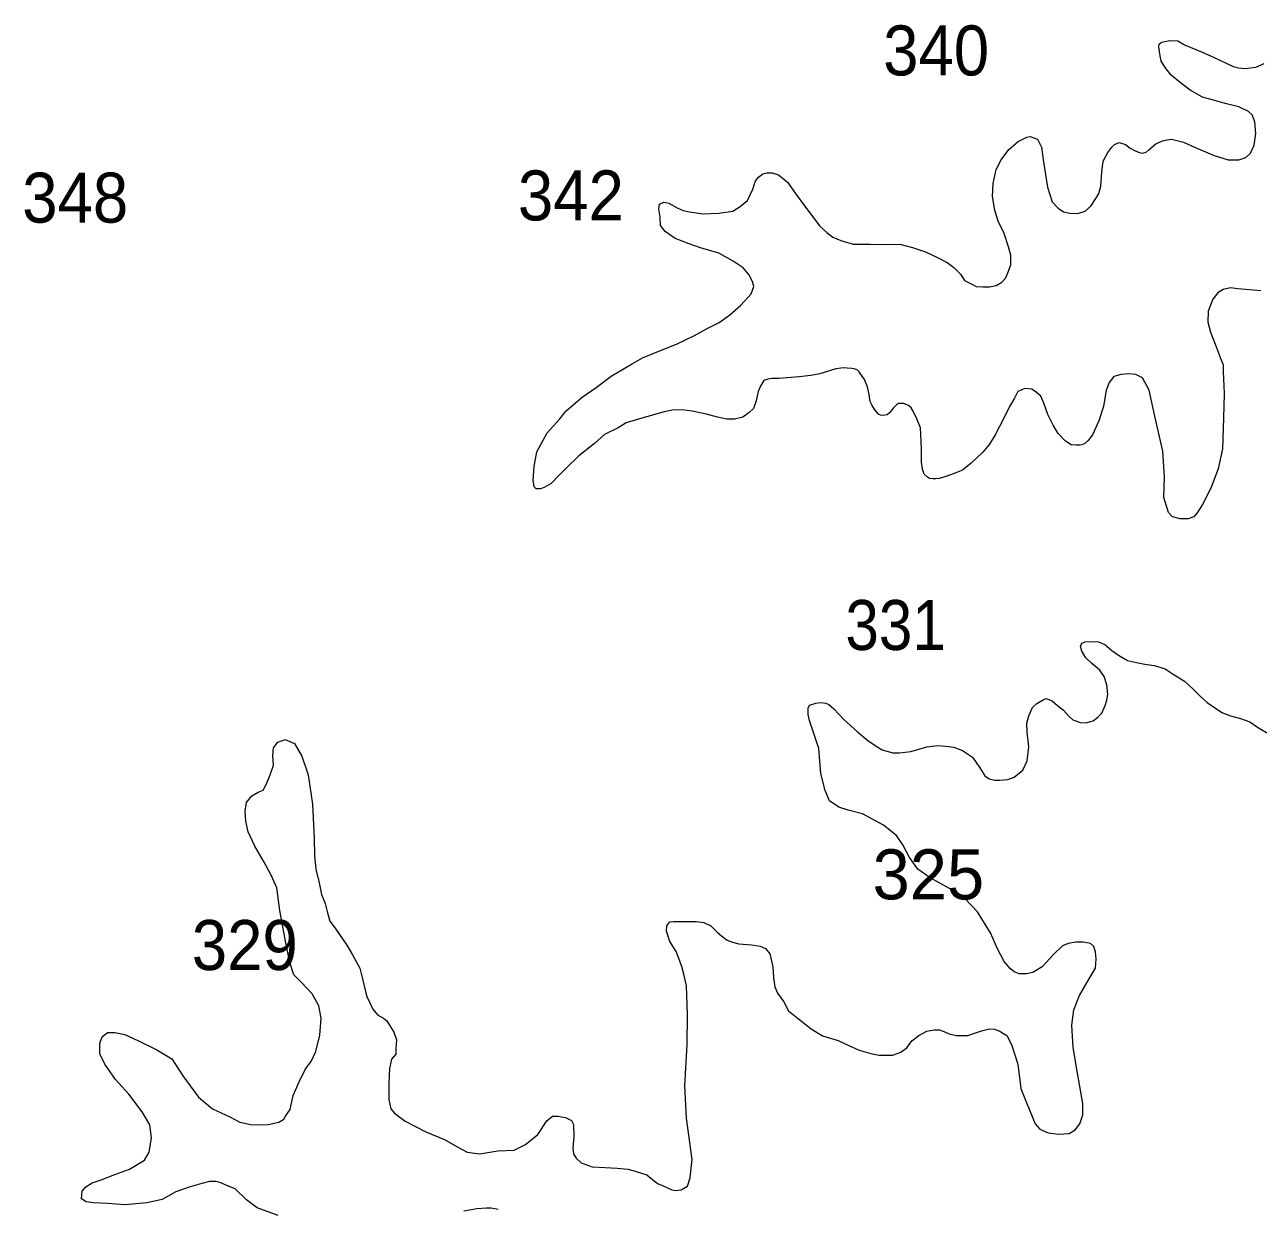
# Model space of a CAD drawing. Extents: x 445.4 to 500, y 8728.7 to 8784.
# Drawn here: x 464.834 to 468.782, y 8737.917 to 8741.707 of the extents above; entities that cross this region are included whole.
import ezdxf

# ---------------------------------------------------------------- set-up
doc = ezdxf.new("R2010")
doc.units = 0
doc.header["$LTSCALE"] = 0.064
doc.layers.add('2', color=7, linetype='Continuous', lineweight=13)
doc.layers.add('21', color=7, linetype='Continuous')

msp = doc.modelspace()

# ---------------------------------------------------------------- linework, layer by layer
at = {"layer": '2'}
for points in [[(468.4106, 8741.2963), (468.4239, 8741.2992), (468.4327, 8741.3081), (468.4547, 8741.3257), (468.4753, 8741.3359), (468.49, 8741.3389), (468.5048, 8741.3403), (468.543, 8741.3315), (468.5783, 8741.3154), (468.6415, 8741.289), (468.6864, 8741.2742), (468.7202, 8741.2742), (468.7423, 8741.2816), (468.757, 8741.2963), (468.7688, 8741.3212), (468.7746, 8741.3594), (468.7717, 8741.3961), (468.7629, 8741.4181), (468.7511, 8741.4298), (468.7202, 8741.4445), (468.6805, 8741.4533), (468.6349, 8741.4665), (468.604, 8741.4753), (468.5643, 8741.4974), (468.532, 8741.5223), (468.5038, 8741.5452), (468.4876, 8741.5658), (468.4714, 8741.5907), (468.467, 8741.6142), (468.4641, 8741.6362), (468.4656, 8741.645), (468.4729, 8741.6509), (468.4994, 8741.6568), (468.5244, 8741.6553), (468.5464, 8741.6421), (468.6009, 8741.6201), (468.6406, 8741.6025), (468.6773, 8741.5849), (468.7023, 8741.5731), (468.7185, 8741.5687), (468.7406, 8741.5672), (468.7744, 8741.5716), (468.8009, 8741.5834)], [(467.0162, 8740.7334), (467.0574, 8740.754), (467.0912, 8740.7789), (467.1265, 8740.8097), (467.1589, 8740.8464), (467.168, 8740.8693), (467.1636, 8740.8854), (467.1518, 8740.9074), (467.1342, 8740.9294), (467.1018, 8740.95), (467.0563, 8740.9764), (466.9974, 8740.9926), (466.9607, 8741.0058), (466.9165, 8741.0234), (466.8842, 8741.0454), (466.8695, 8741.0645), (466.8678, 8741.0918), (466.8634, 8741.1182), (466.8663, 8741.1329), (466.8796, 8741.1387), (466.8957, 8741.1358), (466.9222, 8741.1211), (466.9413, 8741.1123), (466.9619, 8741.1079), (467.0046, 8741.1021), (467.056, 8741.1035), (467.1002, 8741.1109), (467.1237, 8741.1255), (467.1472, 8741.1446), (467.1649, 8741.1813), (467.1737, 8741.2077), (467.1825, 8741.2195), (467.1972, 8741.2298), (467.209, 8741.2327), (467.2266, 8741.2327), (467.2472, 8741.2268), (467.2752, 8741.2033), (467.3031, 8741.1637), (467.3296, 8741.127), (467.3796, 8741.0624), (467.4016, 8741.0419), (467.4208, 8741.0272), (467.4458, 8741.0169), (467.4863, 8741.0047), (467.5393, 8741.0047), (467.5893, 8741.0033), (467.6349, 8741.0047), (467.676, 8740.9945), (467.7172, 8740.9798), (467.7555, 8740.9622), (467.7863, 8740.946), (467.8084, 8740.9299), (467.829, 8740.9093), (467.8422, 8740.8888), (467.8672, 8740.8756), (467.879, 8740.8697), (467.901, 8740.8682), (467.9216, 8740.8682), (467.9437, 8740.8726), (467.9613, 8740.8829), (467.9746, 8740.8976), (467.9834, 8740.9181), (467.9908, 8740.9387), (467.9908, 8740.9695), (467.9834, 8740.9959), (467.9687, 8741.0385), (467.9496, 8741.0781), (467.9393, 8741.1134), (467.9319, 8741.1574), (467.9334, 8741.1985), (467.9437, 8741.244), (467.9591, 8741.2743), (467.9841, 8741.3081), (468.0135, 8741.333), (468.0415, 8741.3477), (468.0518, 8741.3492), (468.0753, 8741.3403), (468.0886, 8741.3154), (468.0944, 8741.2684), (468.1077, 8741.1877), (468.1224, 8741.1407), (468.1415, 8741.1202), (468.1591, 8741.1084), (468.1797, 8741.104), (468.2047, 8741.1026), (468.2283, 8741.1099), (468.2459, 8741.126), (468.265, 8741.1539), (468.2724, 8741.1671), (468.2783, 8741.1906), (468.2812, 8741.2347), (468.2856, 8741.2699), (468.3003, 8741.2978), (468.3136, 8741.3154), (468.3224, 8741.3242), (468.3371, 8741.3301), (468.3577, 8741.3242), (468.3724, 8741.3125), (468.3886, 8741.3036), (468.4018, 8741.2978), (468.4106, 8741.2963)], [(468.7901, 8740.8559), (468.7171, 8740.8614), (468.6934, 8740.865), (468.6696, 8740.8596), (468.6532, 8740.8486), (468.6368, 8740.8286), (468.6222, 8740.7903), (468.6204, 8740.7557), (468.6295, 8740.7229), (468.6459, 8740.6792), (468.6623, 8740.6373), (468.6696, 8740.6191), (468.6696, 8740.5972), (468.6732, 8740.5271), (468.6714, 8740.4487), (468.6678, 8740.3503), (468.6534, 8740.2861), (468.6305, 8740.2237), (468.6034, 8740.1718), (468.5867, 8740.1447), (468.5763, 8740.1323), (468.5576, 8740.126), (468.5326, 8740.126), (468.5076, 8740.1323), (468.4951, 8740.1468), (468.4805, 8740.1946), (468.4826, 8740.2591), (468.4763, 8740.3423), (468.4513, 8740.4545), (468.4326, 8740.5377), (468.4117, 8740.5772), (468.3909, 8740.5876), (468.3659, 8740.5897), (468.343, 8740.5876), (468.3201, 8740.5814), (468.3055, 8740.5627), (468.2951, 8740.5377), (468.2867, 8740.4857), (468.2722, 8740.44), (468.2521, 8740.3947), (468.2381, 8740.3771), (468.2269, 8740.3668), (468.2176, 8740.3631), (468.2111, 8740.3613), (468.1999, 8740.3613), (468.1831, 8740.3631), (468.1654, 8740.3743), (468.1421, 8740.3994), (468.1254, 8740.4254), (468.1086, 8740.4598), (468.0955, 8740.4961), (468.0862, 8740.5184), (468.0723, 8740.5305), (468.0573, 8740.5408), (468.035, 8740.5426), (468.0257, 8740.5389)], [(468.0257, 8740.5389), (468.0126, 8740.5333), (468.0024, 8740.5119), (467.9856, 8740.4859), (467.9679, 8740.4478), (467.9399, 8740.3947), (467.9222, 8740.365), (467.9008, 8740.3389), (467.8635, 8740.3045), (467.836, 8740.2818), (467.809, 8740.2707), (467.7791, 8740.2605), (467.7605, 8740.2549), (467.7503, 8740.2539), (467.7409, 8740.2539), (467.7298, 8740.2549), (467.7232, 8740.2595), (467.713, 8740.2688), (467.7074, 8740.2846), (467.7046, 8740.307), (467.7046, 8740.3488), (467.7027, 8740.3962), (467.7009, 8740.4176), (467.6897, 8740.4455), (467.6776, 8740.4703), (467.6711, 8740.4815), (467.6627, 8740.4889), (467.6552, 8740.4917), (467.6468, 8740.4945), (467.6375, 8740.4954), (467.631, 8740.4945), (467.6245, 8740.4908), (467.6133, 8740.4796), (467.603, 8740.4666), (467.5946, 8740.4592), (467.5872, 8740.4573), (467.5807, 8740.4564), (467.5732, 8740.4573), (467.5667, 8740.461), (467.5546, 8740.475), (467.5462, 8740.4889), (467.5406, 8740.5019), (467.5369, 8740.5243), (467.5313, 8740.5484), (467.522, 8740.5717), (467.5052, 8740.5959), (467.4987, 8740.6024), (467.4921, 8740.6052), (467.4819, 8740.607), (467.4661, 8740.608), (467.4549, 8740.6089), (467.4308, 8740.6062), (467.3796, 8740.5904), (467.3498, 8740.5848), (467.3134, 8740.5802), (467.2474, 8740.5745), (467.2254, 8740.5745), (467.2122, 8740.573), (467.2004, 8740.5686), (467.1901, 8740.5524), (467.1813, 8740.5334), (467.1754, 8740.504), (467.1666, 8740.479), (467.1533, 8740.4658), (467.1327, 8740.4512), (467.1063, 8740.4453), (467.0813, 8740.4453), (467.0518, 8740.4512), (467.0166, 8740.4614), (466.971, 8740.4702), (466.9386, 8740.4746), (466.9063, 8740.4732), (466.8768, 8740.4673), (466.7915, 8740.4423), (466.7592, 8740.4335), (466.7342, 8740.4174), (466.6901, 8740.3954), (466.6577, 8740.3675), (466.6077, 8740.3279), (466.5673, 8740.2876), (466.5453, 8740.2656), (466.5188, 8740.2392), (466.4967, 8740.226), (466.485, 8740.2216), (466.4717, 8740.2216), (466.4644, 8740.2289), (466.4614, 8740.2495), (466.4644, 8740.2935), (466.4732, 8740.3405), (466.507, 8740.4007), (466.5467, 8740.4462), (466.5673, 8740.4711), (466.6188, 8740.5152), (466.6629, 8740.546), (466.7118, 8740.5822), (466.7765, 8740.6204), (466.8118, 8740.6409), (466.8692, 8740.6644), (466.9206, 8740.685), (466.978, 8740.7129), (467.0162, 8740.7334)], [(468.1892, 8739.4832), (468.2135, 8739.4747), (468.2305, 8739.4735), (468.2535, 8739.4795), (468.2693, 8739.4917), (468.2814, 8739.5038), (468.2923, 8739.5292), (468.2972, 8739.5461), (468.3008, 8739.5643), (468.2972, 8739.5946), (468.2887, 8739.6212), (468.2753, 8739.6418), (468.2499, 8739.6636), (468.2305, 8739.6818), (468.2174, 8739.703), (468.2137, 8739.7187), (468.2174, 8739.7284), (468.2283, 8739.732), (468.2489, 8739.7332), (468.2708, 8739.732), (468.2914, 8739.7236), (468.3132, 8739.7042), (468.3351, 8739.6897), (468.3642, 8739.6727), (468.3921, 8739.6666), (468.4188, 8739.6606), (468.4491, 8739.657), (468.4843, 8739.6461), (468.5097, 8739.6291), (468.5461, 8739.6061), (468.5728, 8739.5819), (468.5973, 8739.5573), (468.6191, 8739.5379), (468.6422, 8739.5222), (468.6652, 8739.5065), (468.6931, 8739.4956), (468.7259, 8739.4871), (468.755, 8739.4762), (468.7793, 8739.4592), (468.8195, 8739.4358)], [(467.9776, 8738.473), (467.9925, 8738.4446), (468.0131, 8738.3808), (468.0228, 8738.3038), (468.0421, 8738.2556), (468.0686, 8738.1906), (468.0831, 8738.1737), (468.1096, 8738.1617), (468.1434, 8738.1569), (468.1772, 8738.1593), (468.1965, 8738.1713), (468.211, 8738.1906), (468.2206, 8738.2195), (468.2206, 8738.2556), (468.2037, 8738.3519), (468.1901, 8738.4341), (468.1861, 8738.5056), (468.192, 8738.5552), (468.2099, 8738.6008), (468.2378, 8738.6485), (468.2617, 8738.6882), (468.2636, 8738.718), (468.2617, 8738.7398), (468.2557, 8738.7577), (468.2457, 8738.7676), (468.2219, 8738.7716), (468.198, 8738.7716), (468.1741, 8738.7676), (468.1562, 8738.7596), (468.1264, 8738.7319), (468.0906, 8738.6922), (468.0608, 8738.6743), (468.0409, 8738.6703), (468.017, 8738.6703), (468.0011, 8738.6763), (467.9892, 8738.6862), (467.9693, 8738.71), (467.9474, 8738.7497), (467.9255, 8738.8013), (467.8838, 8738.8688), (467.844, 8738.9105), (467.7938, 8738.9436), (467.7322, 8738.9773), (467.6924, 8739.0051), (467.6665, 8739.0428), (467.6447, 8739.0825), (467.6248, 8739.1123), (467.583, 8739.146), (467.5154, 8739.1818), (467.4697, 8739.1937), (467.4398, 8739.2036), (467.41, 8739.2234), (467.3961, 8739.2572), (467.3822, 8739.3108), (467.376, 8739.391), (467.3621, 8739.4327), (467.3461, 8739.4804), (467.3422, 8739.5002), (467.3422, 8739.5201), (467.3461, 8739.53), (467.366, 8739.536), (467.3819, 8739.5379), (467.3979, 8739.536), (467.4078, 8739.532), (467.4237, 8739.5181), (467.4555, 8739.4843), (467.4993, 8739.4446), (467.5331, 8739.4169), (467.5589, 8739.399), (467.5788, 8739.3871), (467.6126, 8739.3772), (467.6345, 8739.3772), (467.6703, 8739.3811), (467.722, 8739.397), (467.7558, 8739.401), (467.7817, 8739.399), (467.8075, 8739.395), (467.8354, 8739.3851), (467.8672, 8739.3633), (467.8911, 8739.3295), (467.907, 8739.3037), (467.9209, 8739.2938), (467.9388, 8739.2898), (467.9547, 8739.2898), (467.9806, 8739.2918), (468.0005, 8739.2997), (468.0283, 8739.3216), (468.0422, 8739.3513), (468.0482, 8739.397), (468.0424, 8739.4432), (468.0412, 8739.4723), (468.0485, 8739.4953), (468.0594, 8739.5219), (468.074, 8739.5352), (468.0934, 8739.5474), (468.1031, 8739.551), (468.1225, 8739.5437), (468.1395, 8739.5292), (468.1589, 8739.5134), (468.1747, 8739.4953), (468.1892, 8739.4832)], [(465.0998, 8737.9354), (465.0543, 8737.9373), (465.0315, 8737.941), (465.0163, 8737.9505), (465.0182, 8737.9751), (465.0296, 8737.9884), (465.0505, 8738.0017), (465.079, 8738.0111), (465.1226, 8738.0282), (465.17, 8738.0452), (465.2175, 8738.0736), (465.2327, 8738.1001), (465.2403, 8738.1456), (465.2346, 8738.1873), (465.2099, 8738.2289), (465.1681, 8738.2857), (465.1245, 8738.3324), (465.0904, 8738.3817), (465.0752, 8738.4139), (465.0752, 8738.448), (465.0828, 8738.4688), (465.0998, 8738.4821), (465.1226, 8738.4821), (465.1549, 8738.4764), (465.1985, 8738.4555), (465.2573, 8738.4271), (465.3048, 8738.3987), (465.3408, 8738.3438), (465.3902, 8738.2756), (465.4357, 8738.2378), (465.4907, 8738.2131), (465.523, 8738.1961), (465.5572, 8738.1885), (465.5837, 8738.1866), (465.6141, 8738.1885), (465.6482, 8738.1961), (465.6634, 8738.2056), (465.6691, 8738.215), (465.6843, 8738.2359), (465.6938, 8738.2813), (465.7128, 8738.3249), (465.7336, 8738.3665), (465.7507, 8738.3893), (465.7659, 8738.4215), (465.7792, 8738.4745), (465.7834, 8738.5286), (465.7758, 8738.5683), (465.7549, 8738.6062), (465.7208, 8738.6422), (465.6961, 8738.6668), (465.6828, 8738.7066), (465.6695, 8738.7748), (465.6506, 8738.8732), (465.6411, 8738.9452), (465.624, 8738.9842), (465.6012, 8739.0277), (465.5709, 8739.0789), (465.55, 8739.1243), (465.5424, 8739.1584), (465.5403, 8739.1921), (465.5444, 8739.2187), (465.5608, 8739.2392), (465.5814, 8739.2515), (465.5978, 8739.2577), (465.608, 8739.2781), (465.6204, 8739.3068), (465.6306, 8739.3376), (465.6286, 8739.3683), (465.6306, 8739.3929), (465.645, 8739.4113), (465.6676, 8739.4195), (465.6984, 8739.4072), (465.7209, 8739.3662), (465.7415, 8739.3068), (465.7558, 8739.2126), (465.7603, 8739.1031), (465.7616, 8739.049), (465.7666, 8739.005), (465.7767, 8738.961), (465.7843, 8738.9245), (465.7956, 8738.8956), (465.8032, 8738.8654), (465.8107, 8738.839), (465.8284, 8738.8163), (465.8651, 8738.7616), (465.884, 8738.7314), (465.9067, 8738.6886), (465.9155, 8738.6547), (465.9243, 8738.6182), (465.9294, 8738.5981), (465.9482, 8738.5571), (465.9633, 8738.5395), (465.9822, 8738.5282), (465.9936, 8738.5194), (466.0154, 8738.4839), (466.0245, 8738.4589), (466.0222, 8738.4338), (466.0222, 8738.4133), (466.0086, 8738.3974), (466.0017, 8738.3678), (465.9994, 8738.32)], [(465.9994, 8738.32), (465.9994, 8738.2676), (466.0063, 8738.238), (466.0177, 8738.2244), (466.0519, 8738.1993), (466.1181, 8738.1652), (466.1774, 8738.1401), (466.2207, 8738.1151), (466.2503, 8738.0992), (466.2914, 8738.0946), (466.3484, 8738.1037), (466.4009, 8738.106), (466.4374, 8738.1242), (466.4762, 8738.1561), (466.5055, 8738.1998), (466.5232, 8738.2147), (466.5421, 8738.2147), (466.5652, 8738.2107), (466.5842, 8738.2012), (466.5909, 8738.1877), (466.5923, 8738.1484), (466.5882, 8738.1133), (466.5909, 8738.0943), (466.5991, 8738.0808), (466.6153, 8738.0659), (466.6506, 8738.0524), (466.6926, 8738.051), (466.7306, 8738.0483), (466.7658, 8738.0456), (466.7916, 8738.0375), (466.8254, 8738.0267), (466.8498, 8738.0064), (466.862, 8737.9983), (466.8756, 8737.9928), (466.9052, 8737.9792), (466.9186, 8737.9775), (466.9353, 8737.9792), (466.9554, 8737.9909), (466.9638, 8738.0176), (466.9705, 8738.076), (466.9521, 8738.2079), (466.947, 8738.3115), (466.9546, 8738.4443), (466.9559, 8738.539), (466.9519, 8738.6323), (466.9451, 8738.6648), (466.937, 8738.6941), (466.9194, 8738.7414), (466.8991, 8738.7739), (466.8882, 8738.8064), (466.8896, 8738.8239), (466.8991, 8738.8361), (466.9113, 8738.8375), (466.9302, 8738.8375), (466.9587, 8738.8375), (466.9845, 8738.8375), (467.0075, 8738.8348), (467.0306, 8738.8239), (467.0509, 8738.8036), (467.0644, 8738.7915), (467.0821, 8738.7779), (467.0997, 8738.7712), (467.12, 8738.7658), (467.1607, 8738.7631), (467.1878, 8738.759), (467.2054, 8738.7509), (467.219, 8738.7346), (467.2285, 8738.6927), (467.2312, 8738.6575), (467.2352, 8738.6291), (467.2434, 8738.6088), (467.2637, 8738.5804), (467.2786, 8738.552), (467.3057, 8738.5304), (467.351, 8738.4947), (467.3876, 8738.4717), (467.4377, 8738.4568), (467.4716, 8738.4406), (467.5055, 8738.4257), (467.5421, 8738.4149), (467.5692, 8738.4095), (467.6112, 8738.4095), (467.636, 8738.4189), (467.6577, 8738.4338), (467.674, 8738.4554), (467.6957, 8738.473), (467.7079, 8738.4798), (467.7214, 8738.4866), (467.7445, 8738.4906), (467.7621, 8738.4906), (467.7757, 8738.4852), (467.7933, 8738.4784), (467.815, 8738.473), (467.8299, 8738.473), (467.8529, 8738.473), (467.8773, 8738.4811), (467.9004, 8738.4893), (467.9221, 8738.4947), (467.9383, 8738.4933), (467.9532, 8738.4879), (467.9776, 8738.473)], [(465.6452, 8737.8974), (465.5788, 8737.922), (465.5446, 8737.9467), (465.5078, 8737.9827), (465.4831, 8737.9922), (465.4623, 8738.0017), (465.4471, 8738.0054), (465.4262, 8738.0054), (465.4015, 8737.9998), (465.3636, 8737.9884), (465.3181, 8737.9732), (465.2744, 8737.9486), (465.2251, 8737.9373), (465.1549, 8737.9316), (465.0998, 8737.9354)], [(466.3501, 8737.9163), (466.3274, 8737.9201), (466.3122, 8737.9201), (466.2818, 8737.9182), (466.2401, 8737.9106)]]:
    msp.add_lwpolyline(points, dxfattribs=at)

# ---------------------------------------------------------------- texts
at = {"layer": '21'}
for s, width, p in [('340', 0.95, (467.5818, 8741.5447)), ('348', 0.95, (464.8266, 8741.0737)), ('342', 0.95, (466.4129, 8741.0808)), ('331', 0.9, (467.4609, 8739.7063)), ('329', 0.95, (465.3692, 8738.6824))]:
    msp.add_text(s, height=0.16, dxfattribs=dict(at, width=width)).set_placement(p)
msp.add_text('325', height=0.16, dxfattribs=at).set_placement((467.548, 8738.9085))

doc.saveas('drawing.dxf')
